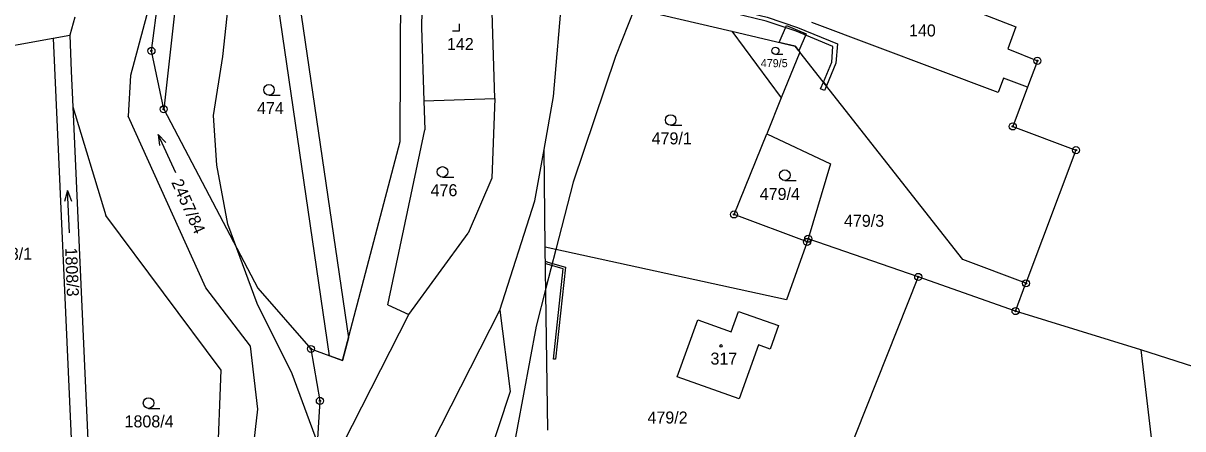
# Model space of a CAD drawing. Extents: x -546762 to -540209, y -1046851 to -1035694.
# Drawn here: x -542613 to -542448.6, y -1039277.1 to -1039219.7 of the extents above; entities that cross this region are included whole.
import ezdxf

# ---------------------------------------------------------------- set-up
doc = ezdxf.new("R2010")
doc.units = 0
for name, color, linetype in [('Vrstva 1', 7, 'Continuous'), ('Vrstva 18', 7, 'Continuous'), ('Vrstva 19', 7, 'Continuous'), ('Vrstva 24', 7, 'Continuous'), ('Vrstva 25', 7, 'Continuous'), ('Vrstva 3', 7, 'Continuous'), ('Vrstva 30', 7, 'Continuous'), ('Vrstva 37', 7, 'Continuous'), ('Vrstva 4', 7, 'Continuous'), ('Vrstva 52', 7, 'Continuous')]:
    doc.layers.add(name, color=color, linetype=linetype)

msp = doc.modelspace()

# ---------------------------------------------------------------- linework, layer by layer
at = {"layer": 'Vrstva 1'}
for p, q in [((-542594.85, -1039223.57), (-542592.78, -1039208.18)), ((-542593.11, -1039231.84), (-542594.85, -1039223.57)), ((-542512.25, -1039246.75), (-542507.61, -1039235.31)), ((-542501.89, -1039250.64), (-542512.25, -1039246.75)), ((-542501.89, -1039250.64), (-542504.83, -1039258.85)), ((-542501.73, -1039250.2), (-542501.89, -1039250.64)), ((-542486.14, -1039255.6), (-542501.73, -1039250.2)), ((-542572.24, -1039265.81), (-542570.97, -1039273.17)), ((-542570.97, -1039273.17), (-542571.53, -1039282.43))]:
    msp.add_line(p, q, dxfattribs=at)
for points in [[(-542592.78, -1039208.18), (-542597.82, -1039227.04)], [(-542590.43, -1039207.96), (-542593.11, -1039231.84)], [(-542556.4, -1039213.07), (-542556.54, -1039220.28)], [(-542546.17, -1039230.31), (-542546.7, -1039213.51)], [(-542559.58, -1039236.41), (-542559.48, -1039214.01)], [(-542537.87, -1039230.05), (-542536.58, -1039215.15)], [(-542536.58, -1039215.15), (-542512.55, -1039220.8)], [(-542476.95, -1039218.37), (-542472.29, -1039220.15)], [(-542605.7, -1039218.8), (-542606.44, -1039221.35)], [(-542608.8, -1039221.77), (-542606.44, -1039221.35)], [(-542606.44, -1039221.35), (-542606.23, -1039226.43)], [(-542556.54, -1039220.28), (-542556.21, -1039230.63)], [(-542512.55, -1039220.8), (-542505.55, -1039230.23)], [(-542512.55, -1039220.8), (-542503.56, -1039222.92)], [(-542472.29, -1039220.15), (-542473.44, -1039223.3)], [(-542619.28, -1039223.65), (-542608.8, -1039221.77)], [(-542608.8, -1039221.77), (-542606.1, -1039281.68)], [(-542503.56, -1039222.92), (-542502.92, -1039223.74)], [(-542473.44, -1039223.3), (-542469.24, -1039224.98)], [(-542502.92, -1039223.74), (-542505.55, -1039230.23)], [(-542479.82, -1039253.14), (-542502.92, -1039223.74)], [(-542469.24, -1039224.98), (-542470.65, -1039228.72)], [(-542606.23, -1039226.43), (-542606, -1039231.49)], [(-542597.82, -1039227.04), (-542598.13, -1039232.81)], [(-542470.65, -1039228.72), (-542472.73, -1039234.28)], [(-542606, -1039231.49), (-542601.34, -1039246.91)], [(-542606, -1039231.49), (-542603.73, -1039281.85)], [(-542556.21, -1039230.63), (-542546.17, -1039230.31)], [(-542556.21, -1039230.63), (-542556.08, -1039234.74)], [(-542546.17, -1039230.31), (-542546.6, -1039241.61)], [(-542539.19, -1039237.53), (-542537.87, -1039230.05)], [(-542505.55, -1039230.23), (-542507.61, -1039235.31)], [(-542587.16, -1039257.15), (-542598.13, -1039232.81)], [(-542593.11, -1039231.84), (-542579.79, -1039257.22)], [(-542561.32, -1039259.55), (-542556.08, -1039234.74)], [(-542472.73, -1039234.28), (-542463.77, -1039237.64)], [(-542567.77, -1039267.45), (-542559.58, -1039236.41)], [(-542507.61, -1039235.31), (-542498.57, -1039239.59)], [(-542540.48, -1039244.84), (-542539.19, -1039237.53)], [(-542539.01, -1039251.37), (-542539.19, -1039237.53)], [(-542463.77, -1039237.64), (-542470.86, -1039256.51)], [(-542498.57, -1039239.59), (-542501.73, -1039250.2)], [(-542546.6, -1039241.61), (-542549.95, -1039249.4)], [(-542545.45, -1039260.3), (-542540.48, -1039244.84)], [(-542584.97, -1039268.84), (-542601.34, -1039246.91)], [(-542558.36, -1039260.91), (-542549.95, -1039249.4)], [(-542504.83, -1039258.85), (-542539.01, -1039251.37)], [(-542538.66, -1039277.31), (-542539.01, -1039251.37)], [(-542470.86, -1039256.51), (-542479.82, -1039253.14)], [(-542486.14, -1039255.6), (-542499.44, -1039289.01)], [(-542472.34, -1039260.45), (-542486.14, -1039255.6)], [(-542580.82, -1039265.42), (-542587.16, -1039257.15)], [(-542579.79, -1039257.22), (-542572.24, -1039265.81)], [(-542472.34, -1039260.45), (-542470.86, -1039256.51)], [(-542561.32, -1039259.55), (-542558.36, -1039260.91)], [(-542567.67, -1039279.19), (-542558.36, -1039260.91)], [(-542555.14, -1039279.37), (-542545.45, -1039260.3)], [(-542545.45, -1039260.3), (-542543.97, -1039271.83)], [(-542512.64, -1039263.4), (-542511.62, -1039260.49)], [(-542511.62, -1039260.49), (-542505.94, -1039262.51)], [(-542454.56, -1039265.95), (-542472.34, -1039260.45)], [(-542520.3, -1039269.75), (-542517.39, -1039261.71)], [(-542517.39, -1039261.71), (-542512.64, -1039263.4)], [(-542505.94, -1039262.51), (-542507.13, -1039265.85)], [(-542579.76, -1039274.36), (-542580.82, -1039265.42)], [(-542572.24, -1039265.81), (-542567.77, -1039267.45)], [(-542508.79, -1039265.24), (-542511.54, -1039272.9)], [(-542507.13, -1039265.85), (-542508.79, -1039265.24)], [(-542423.21, -1039275.98), (-542454.56, -1039265.95)], [(-542454.56, -1039265.95), (-542449.17, -1039311.72)], [(-542585.48, -1039282.22), (-542584.97, -1039268.84)], [(-542511.54, -1039272.9), (-542520.3, -1039269.75)], [(-542543.97, -1039271.83), (-542547.35, -1039282.02)], [(-542581.55, -1039290), (-542579.76, -1039274.36)]]:
    msp.add_lwpolyline(points, dxfattribs=at)
at = {"layer": 'Vrstva 24'}
for centre, radius in [((-542594.85, -1039223.57), 0.5), ((-542594.85, -1039223.57), 0.1), ((-542469.24, -1039224.98), 0.5), ((-542469.24, -1039224.98), 0.1), ((-542593.11, -1039231.84), 0.5), ((-542593.11, -1039231.84), 0.1), ((-542472.73, -1039234.28), 0.5), ((-542472.73, -1039234.28), 0.1), ((-542463.77, -1039237.64), 0.5), ((-542463.77, -1039237.64), 0.1), ((-542512.25, -1039246.75), 0.5), ((-542512.25, -1039246.75), 0.1), ((-542501.89, -1039250.64), 0.5), ((-542501.73, -1039250.2), 0.5), ((-542501.89, -1039250.64), 0.1), ((-542501.73, -1039250.2), 0.1), ((-542486.14, -1039255.6), 0.5), ((-542486.14, -1039255.6), 0.1), ((-542470.86, -1039256.51), 0.5), ((-542470.86, -1039256.51), 0.1), ((-542472.34, -1039260.45), 0.5), ((-542472.34, -1039260.45), 0.1), ((-542572.24, -1039265.81), 0.5), ((-542572.24, -1039265.81), 0.1), ((-542570.97, -1039273.17), 0.5), ((-542570.97, -1039273.17), 0.1)]:
    msp.add_circle(centre, radius, dxfattribs=at)
at = {"layer": 'Vrstva 25'}
for p, q in [((-542506.38, -1039224.06), (-542505.31, -1039224.06)), ((-542578.19, -1039229.84), (-542576.59, -1039229.84)), ((-542521.24, -1039234.12), (-542519.64, -1039234.12)), ((-542553.58, -1039241.47), (-542551.98, -1039241.47)), ((-542505.05, -1039241.94), (-542503.45, -1039241.94)), ((-542595.26, -1039274.23), (-542593.66, -1039274.23))]:
    msp.add_line(p, q, dxfattribs=at)
for points in [[(-542552.19, -1039220.74), (-542551.19, -1039220.74), (-542551.19, -1039219.74)], [(-542591.39, -1039240.87), (-542593.89, -1039235.41), (-542593.72, -1039236.98)], [(-542593.89, -1039235.41), (-542592.81, -1039236.57)], [(-542606.48, -1039249.38), (-542606.74, -1039243.38), (-542607.17, -1039244.9)], [(-542606.74, -1039243.38), (-542606.18, -1039244.86)]]:
    msp.add_lwpolyline(points, dxfattribs=at)
for centre, radius in [((-542506.38, -1039223.56), 0.503), ((-542578.19, -1039229.09), 0.75), ((-542521.24, -1039233.37), 0.75), ((-542553.58, -1039240.72), 0.75), ((-542505.05, -1039241.19), 0.75), ((-542514.09, -1039265.38), 0.175), ((-542595.26, -1039273.48), 0.75)]:
    msp.add_circle(centre, radius, dxfattribs=at)
at = {"layer": 'Vrstva 3'}
for points in [[(-542476.95, -1039218.37), (-542472.29, -1039220.15)], [(-542474.82, -1039229.48), (-542501.22, -1039219.56)], [(-542472.29, -1039220.15), (-542473.44, -1039223.3)], [(-542473.44, -1039223.3), (-542469.24, -1039224.98)], [(-542469.24, -1039224.98), (-542470.65, -1039228.72)], [(-542474.06, -1039227.44), (-542474.82, -1039229.48)], [(-542470.65, -1039228.72), (-542474.06, -1039227.44)], [(-542512.64, -1039263.4), (-542511.62, -1039260.49)], [(-542511.62, -1039260.49), (-542505.94, -1039262.51)], [(-542520.3, -1039269.75), (-542517.39, -1039261.71)], [(-542517.39, -1039261.71), (-542512.64, -1039263.4)], [(-542505.94, -1039262.51), (-542507.13, -1039265.85)], [(-542508.79, -1039265.24), (-542511.54, -1039272.9)], [(-542507.13, -1039265.85), (-542508.79, -1039265.24)], [(-542511.54, -1039272.9), (-542520.3, -1039269.75)]]:
    msp.add_lwpolyline(points, dxfattribs=at)
at = {"layer": 'Vrstva 30'}
for points in [[(-542578.95, -1039202.75), (-542574.85, -1039202.88), (-542573.74, -1039202.61), (-542570.15, -1039201.72), (-542570.08, -1039204.8), (-542573.75, -1039205.7), (-542574.53, -1039205.9), (-542575.47, -1039205.87), (-542566.93, -1039264.25), (-542567.77, -1039267.45), (-542569.59, -1039266.78), (-542578.95, -1039202.75)], [(-542526.21, -1039213.87), (-542526.23, -1039213.99), (-542518.43, -1039216.15), (-542507.55, -1039218.79), (-542503.24, -1039220.24), (-542497.59, -1039222.56), (-542497.8, -1039225.31), (-542499.15, -1039228.54), (-542499.57, -1039228), (-542498.4, -1039225.17), (-542498.23, -1039222.94), (-542503.44, -1039220.8), (-542507.71, -1039219.37), (-542518.59, -1039216.73), (-542526.93, -1039214.41), (-542526.8, -1039213.73), (-542526.21, -1039213.87)], [(-542505.83, -1039222.39), (-542504.79, -1039219.98), (-542502.04, -1039221.17), (-542503.07, -1039223.55), (-542503.56, -1039222.92), (-542505.83, -1039222.39)], [(-542499.42, -1039229.2), (-542499.97, -1039228.97), (-542499.57, -1039228)], [(-542499.57, -1039228), (-542499.15, -1039228.54)], [(-542499.15, -1039228.54), (-542499.42, -1039229.2)], [(-542536.46, -1039254.46), (-542538.74, -1039253.81), (-542538.98, -1039253.71), (-542538.98, -1039253.37), (-542538.64, -1039253.52), (-542536.14, -1039254.24), (-542537.54, -1039267.28), (-542537.83, -1039267.25), (-542536.46, -1039254.46)]]:
    msp.add_lwpolyline(points, dxfattribs=at)
at = {"layer": 'Vrstva 37'}
msp.add_circle((-542514.09, -1039265.38), 0.175, dxfattribs=at)
at = {"layer": 'Vrstva 4'}
for points in [[(-542474.82, -1039229.48), (-542501.22, -1039219.56)], [(-542474.06, -1039227.44), (-542474.82, -1039229.48)], [(-542470.65, -1039228.72), (-542474.06, -1039227.44)]]:
    msp.add_lwpolyline(points, dxfattribs=at)
at = {"layer": 'Vrstva 52'}
for points in [[(-542467.54, -1039106.4), (-542473.05, -1039115.93), (-542473.78, -1039117.26), (-542480.57, -1039129.73), (-542485.14, -1039138.11), (-542492.41, -1039151.46), (-542499.46, -1039164.4), (-542504.11, -1039172.94), (-542507.29, -1039178.77), (-542507.82, -1039179.74), (-542511.27, -1039185.71), (-542515.48, -1039193), (-542517.35, -1039196.94), (-542522.54, -1039207.91), (-542525.01, -1039214.14), (-542526.36, -1039217.55), (-542529.07, -1039224.38), (-542535.08, -1039242.17), (-542537.52, -1039251.7), (-542538.93, -1039257.19), (-542540.31, -1039262.57), (-542544.81, -1039286.67)], [(-542569.64, -1039288.23), (-542569.79, -1039284.49), (-542569.92, -1039284.01), (-542570.96, -1039280.05), (-542571.33, -1039279.05), (-542574.88, -1039269.32), (-542579.84, -1039259.38), (-542582.74, -1039251.6), (-542584.03, -1039248.14), (-542585.59, -1039239.77), (-542586.05, -1039232.74), (-542584.75, -1039224.37), (-542583.96, -1039217.31), (-542580.82, -1039207.63), (-542577.81, -1039200.9), (-542577.43, -1039200.05), (-542572.98, -1039192.46), (-542566.81, -1039183.26), (-542561.58, -1039174.11), (-542558.14, -1039165.3), (-542558.11, -1039165.22)]]:
    msp.add_lwpolyline(points, dxfattribs=at)

# ---------------------------------------------------------------- texts
at = {"layer": 'Vrstva 18'}
for s, height, p in [('479/5', 1.14, (-542508.46, -1039225.88)), ('474', 1.7, (-542579.88, -1039232.54)), ('479/1', 1.7, (-542523.93, -1039236.82)), ('476', 1.7, (-542555.27, -1039244.17)), ('479/4', 1.7, (-542508.6, -1039244.7)), ('479/3', 1.7, (-542496.66, -1039248.5)), ('1808/1', 1.7, (-542618.72, -1039253.18)), ('1808/4', 1.7, (-542598.66, -1039276.93)), ('479/2', 1.7, (-542524.52, -1039276.38))]:
    msp.add_text(s, height=height, dxfattribs=at).set_placement(p)
for s, rotation, p in [('2457/84', 294.261, (-542592.07, -1039242.19)), ('1808/3', 272.1452, (-542607.09, -1039251.47))]:
    msp.add_text(s, height=1.7, rotation=rotation, dxfattribs=at).set_placement(p)
at = {"layer": 'Vrstva 19'}
for s, p in [('140', (-542487.44, -1039221.53)), ('142', (-542552.95, -1039223.45)), ('317', (-542515.59, -1039268.03))]:
    msp.add_text(s, height=1.7, dxfattribs=at).set_placement(p)

doc.saveas('drawing.dxf')
